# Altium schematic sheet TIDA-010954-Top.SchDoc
size 431 x 279 mm; Date: Not shown in title block; ApprovedBy: Not shown in title block; CheckedBy: Not shown in title block; Author: Not shown in title block; CompanyName: Not shown in title block; Engineer: Not shown in title block; Organization: Not shown in title block; Address1: Not shown in title block; Address2: Not shown in title block; Address3: Not shown in title block; Address4: Not shown in title block; DocumentNumber: 2; Revision: Use project parameter SCH_Rev; SheetNumber: 1; SheetTotal: 9; PageSetup: Record=PageOptions¦CenterHorizontal=True¦CenterVertical=True¦PrintScale=1.00¦XCorrection=1.00¦YCorrection=1.00¦PrintKind=0¦BorderSize=5000000¦LeftOffset=0¦BottomOffset=0¦Orientation=2¦PaperLength=1000¦PaperWidth=1000¦Scale=100¦PaperSource=15¦PrintQuality=600¦MediaType=1¦DitherType=10¦PaperKind=Letter¦PrintScaleMode=1
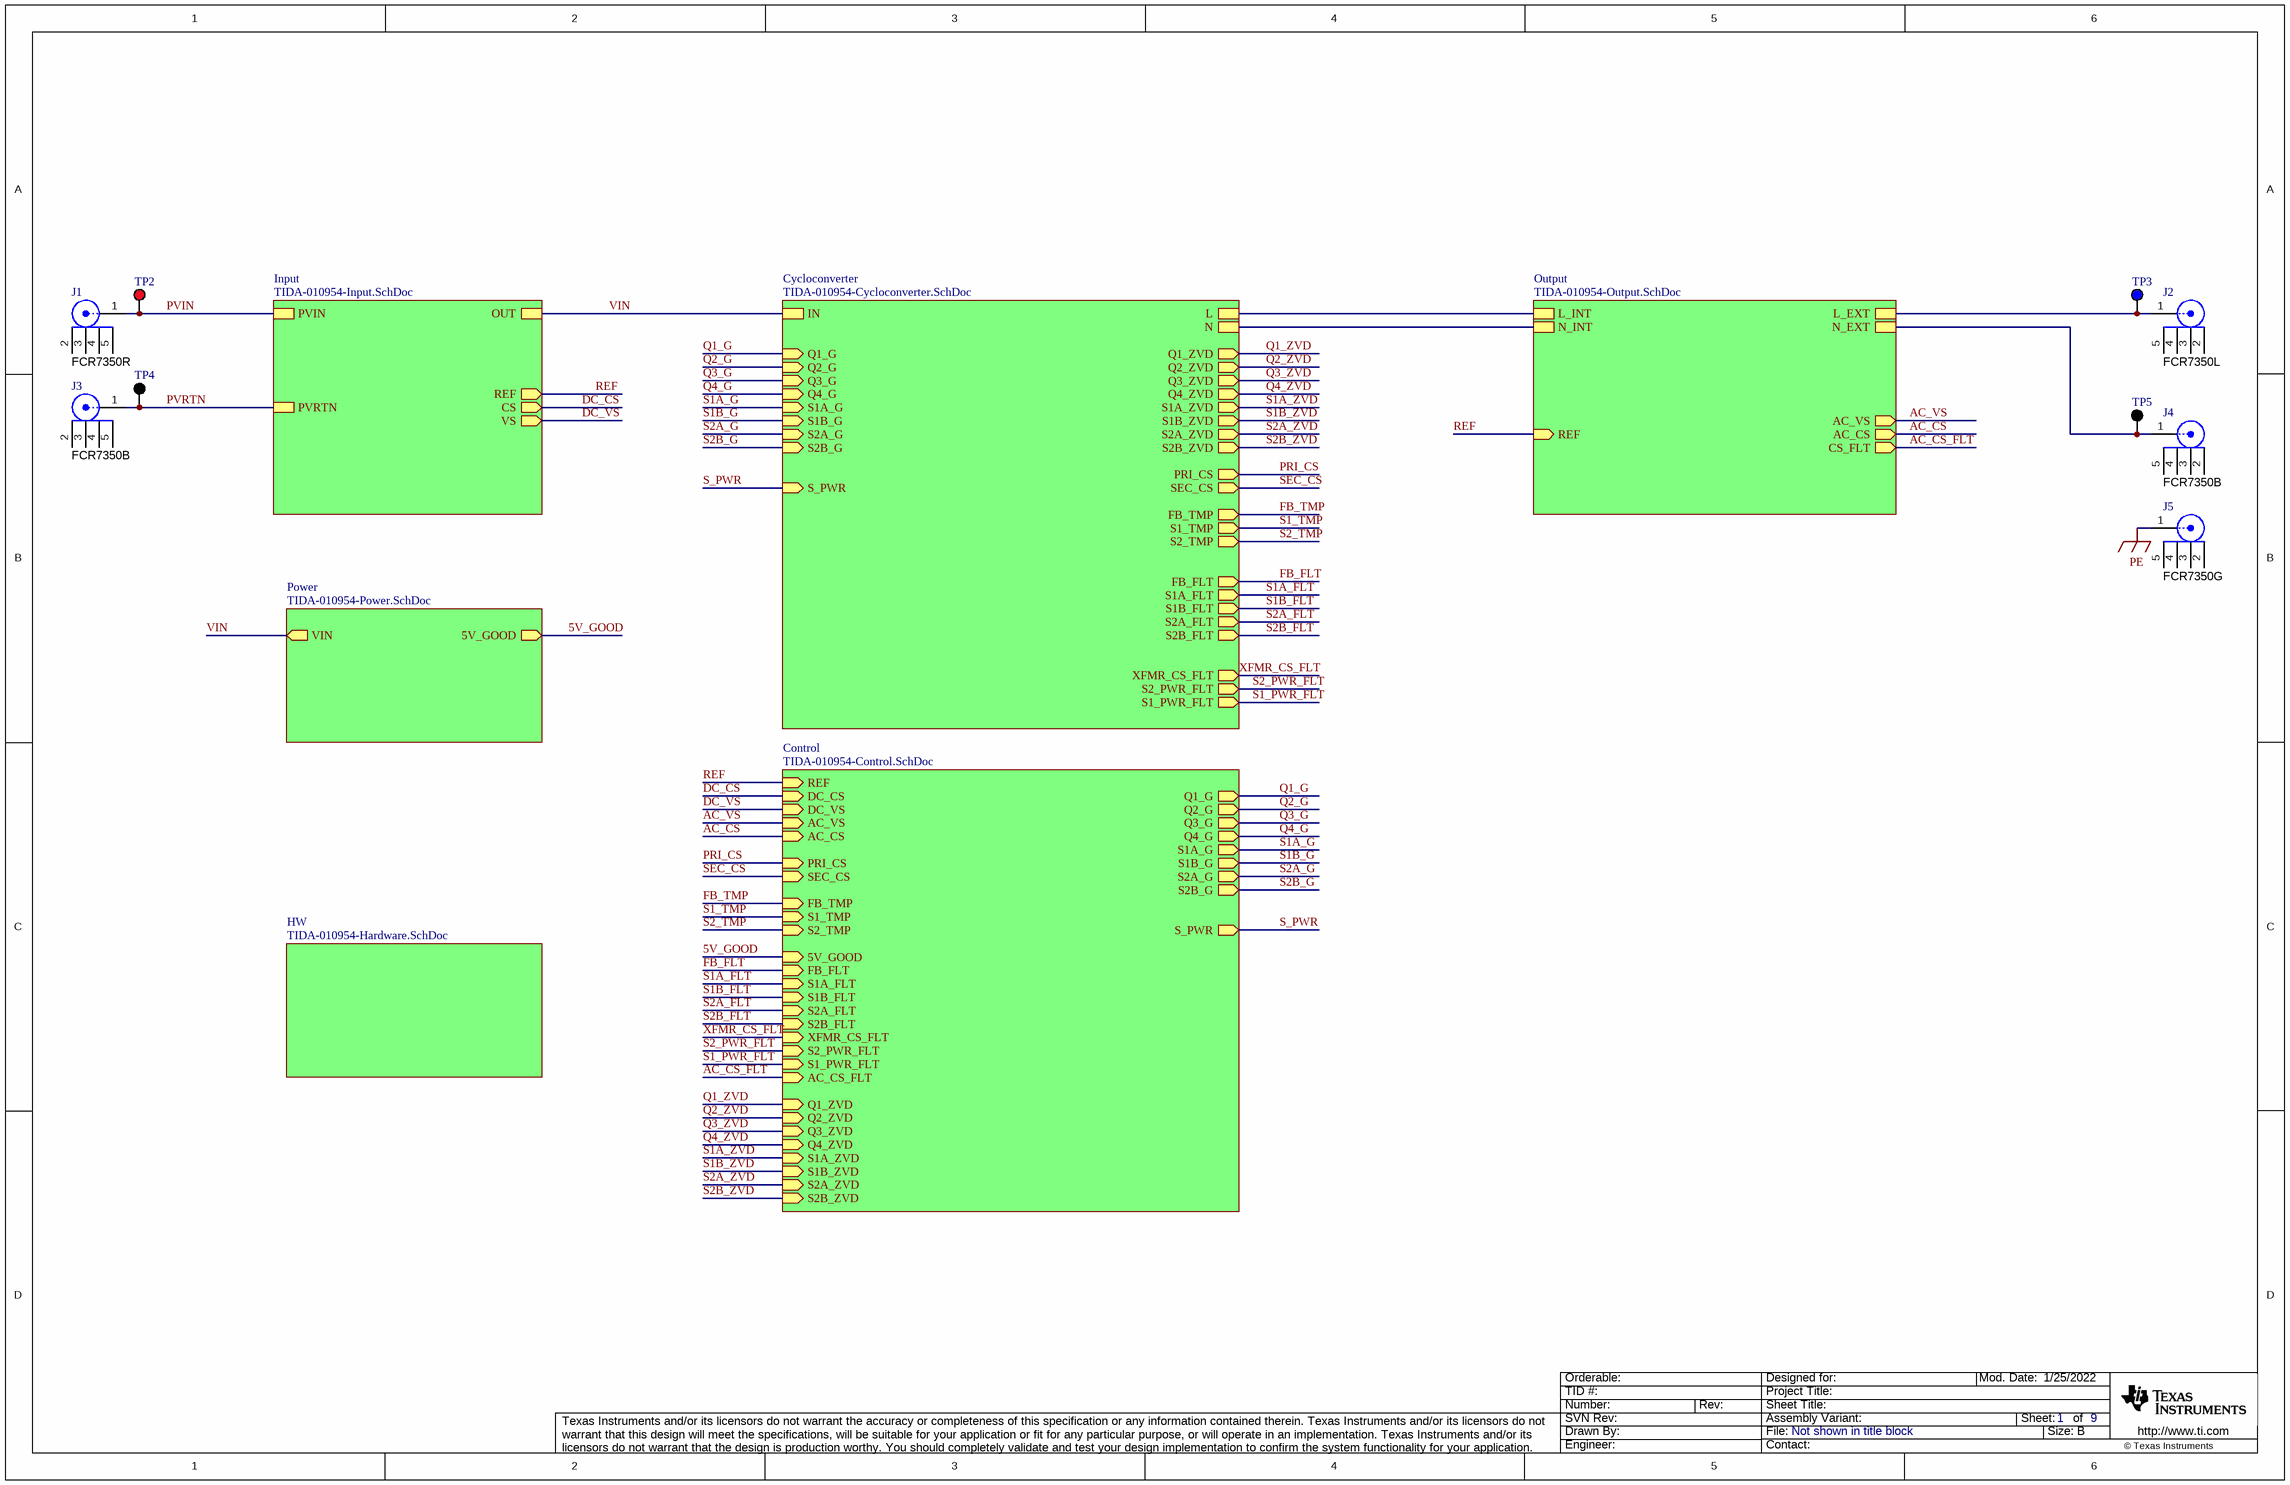
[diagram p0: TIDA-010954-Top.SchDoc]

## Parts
J1  FCR7350R  [Cliff_FCR7350R]
J2  FCR7350L  [FP-FCR7350L_CONN_BANANA_JACK-MFG]
J3  FCR7350B  [Cliff_FCR7350B]
J4  FCR7350B  [Cliff_FCR7350B]
J5  FCR7350G  [FP-FCR7350G_CONN_BANANA_JACK-MFG]
TP2  5010  [Keystone5010]  (value not drawn)
TP3  5127  [Keystone5127]  (value not drawn)
TP4  5011  [Keystone5011]  (value not drawn)
TP5  5011  [Keystone5011]  (value not drawn)

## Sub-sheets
Control = TIDA-010954-Control.SchDoc: Q1_G (out), Q2_G (out), Q3_G (out), Q4_G (out), S1A_G (out), S1B_G (out), S2A_G (out), S2B_G (out), S_PWR (out), 5V_GOOD (in), DC_CS (in), DC_VS (in), REF (in), AC_CS (in), AC_VS (in), PRI_CS (in), SEC_CS (in), FB_FLT (in), S1_PWR_FLT (in), XFMR_CS_FLT (in), S1A_FLT (in), S2_PWR_FLT (in), S2A_FLT (in), AC_CS_FLT (in), S1_TMP (in), S2_TMP (in), FB_TMP (in), Q2_ZVD (in), Q1_ZVD (in), Q4_ZVD (in), Q3_ZVD (in), S1A_ZVD (in), S1B_ZVD (in), S2A_ZVD (in), S2B_ZVD (in), S1B_FLT (in), S2B_FLT (in)
Cycloconverter = TIDA-010954-Cycloconverter.SchDoc: IN, N, L, Q1_G (in), Q2_G (in), Q3_G (in), Q4_G (in), S1A_G (in), S1B_G (in), S2A_G (in), S2B_G (in), S_PWR (in), PRI_CS (out), SEC_CS (out), FB_FLT (out), Q2_ZVD (out), Q1_ZVD (out), Q4_ZVD (out), Q3_ZVD (out), S1_PWR_FLT (out), XFMR_CS_FLT (out), S1A_ZVD (out), S1B_ZVD (out), S1A_FLT (out), S1_TMP (out), S2_PWR_FLT (out), S2A_ZVD (out), S2B_ZVD (out), S2A_FLT (out), S2_TMP (out), FB_TMP (out), S2B_FLT (out), S1B_FLT (out)
HW = TIDA-010954-Hardware.SchDoc: no entries
Input = TIDA-010954-Input.SchDoc: OUT, PVIN, PVRTN, CS (out), VS (out), REF (out)
Output = TIDA-010954-Output.SchDoc: L_INT, N_INT, L_EXT, N_EXT, CS_FLT (out), AC_CS (out), REF (in), AC_VS (out)
Power = TIDA-010954-Power.SchDoc: VIN (out), 5V_GOOD (out)

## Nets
PE: J5.1
5V_GOOD: sheet Power/5V_GOOD, sheet Control/5V_GOOD
AC_CS: sheet Output/AC_CS, sheet Control/AC_CS
AC_CS_FLT: sheet Output/CS_FLT, sheet Control/AC_CS_FLT
AC_VS: sheet Output/AC_VS, sheet Control/AC_VS
DC_CS: sheet Input/CS, sheet Control/DC_CS
DC_VS: sheet Input/VS, sheet Control/DC_VS
FB_FLT: sheet Cycloconverter/FB_FLT, sheet Control/FB_FLT
FB_TMP: sheet Cycloconverter/FB_TMP, sheet Control/FB_TMP
PRI_CS: sheet Cycloconverter/PRI_CS, sheet Control/PRI_CS
PVIN: J1.1 TP2.1 ; sheet Input/PVIN
PVRTN: J3.1 TP4.1 ; sheet Input/PVRTN
Q1_G: sheet Cycloconverter/Q1_G, sheet Control/Q1_G
Q1_ZVD: sheet Cycloconverter/Q1_ZVD, sheet Control/Q1_ZVD
Q2_G: sheet Cycloconverter/Q2_G, sheet Control/Q2_G
Q2_ZVD: sheet Cycloconverter/Q2_ZVD, sheet Control/Q2_ZVD
Q3_G: sheet Cycloconverter/Q3_G, sheet Control/Q3_G
Q3_ZVD: sheet Cycloconverter/Q3_ZVD, sheet Control/Q3_ZVD
Q4_G: sheet Cycloconverter/Q4_G, sheet Control/Q4_G
Q4_ZVD: sheet Cycloconverter/Q4_ZVD, sheet Control/Q4_ZVD
REF: sheet Input/REF, sheet Output/REF, sheet Control/REF
S1_PWR_FLT: sheet Cycloconverter/S1_PWR_FLT, sheet Control/S1_PWR_FLT
S1_TMP: sheet Cycloconverter/S1_TMP, sheet Control/S1_TMP
S1A_FLT: sheet Cycloconverter/S1A_FLT, sheet Control/S1A_FLT
S1A_G: sheet Cycloconverter/S1A_G, sheet Control/S1A_G
S1A_ZVD: sheet Cycloconverter/S1A_ZVD, sheet Control/S1A_ZVD
S1B_FLT: sheet Cycloconverter/S1B_FLT, sheet Control/S1B_FLT
S1B_G: sheet Cycloconverter/S1B_G, sheet Control/S1B_G
S1B_ZVD: sheet Cycloconverter/S1B_ZVD, sheet Control/S1B_ZVD
S2_PWR_FLT: sheet Cycloconverter/S2_PWR_FLT, sheet Control/S2_PWR_FLT
S2_TMP: sheet Cycloconverter/S2_TMP, sheet Control/S2_TMP
S2A_FLT: sheet Cycloconverter/S2A_FLT, sheet Control/S2A_FLT
S2A_G: sheet Cycloconverter/S2A_G, sheet Control/S2A_G
S2A_ZVD: sheet Cycloconverter/S2A_ZVD, sheet Control/S2A_ZVD
S2B_FLT: sheet Cycloconverter/S2B_FLT, sheet Control/S2B_FLT
S2B_G: sheet Cycloconverter/S2B_G, sheet Control/S2B_G
S2B_ZVD: sheet Cycloconverter/S2B_ZVD, sheet Control/S2B_ZVD
S_PWR: sheet Cycloconverter/S_PWR, sheet Control/S_PWR
SEC_CS: sheet Cycloconverter/SEC_CS, sheet Control/SEC_CS
VIN: sheet Power/VIN, sheet Input/OUT, sheet Cycloconverter/IN
XFMR_CS_FLT: sheet Cycloconverter/XFMR_CS_FLT, sheet Control/XFMR_CS_FLT
NetJ2_1: J2.1 TP3.1 ; sheet Output/L_EXT
NetJ4_1: J4.1 TP5.1 ; sheet Output/N_EXT
(unnamed): sheet Output/L_INT, sheet Cycloconverter/L
(unnamed): sheet Output/N_INT, sheet Cycloconverter/N  [a separate net that carries the same name]

Not connected (* = marked no-connect by the designer): J1 2 3 4 5; J2 2 3 4 5; J3 2 3 4 5; J4 2 3 4 5; J5 2 3 4 5

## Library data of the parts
J1 = CMP-0055799-1: Panel Socket, 24A, R/A, Gold, TH; Manufacturer: Cliff Electronic Components; CNHeader: FALSE; Gender: Female; Voltage_V: 1kV
J2 = CMP-0098295-2: Banana Test Connector, 4mm, Socket, PCB Mount, 24 A, 1 kV, Gold Plated Contacts, Blue; Manufacturer: CLIFF Electronic Components; Current_A: 24A; Voltage_V: 1kV; AEC Qualified: No; Conn Orientation: Right Angle; SizeZ_mm: 11.6mm; Standoff Height: 0.7mm
J3 J4 = CMP-0055798-1: Panel Socket, 24A, R/A, Gold, TH; Manufacturer: Cliff Electronic Components; CNHeader: FALSE; Gender: Female; Voltage_V: 1kV
J5 = CMP-0098294-2: Banana Test Connector, Socket, PCB Mount, 24 A, 1 kV, Gold Plated Contacts, Green; Manufacturer: CLIFF Electronic Components; Current_A: 24A; Voltage_V: 1kV; AEC Qualified: No; Conn Orientation: Right Angle; SizeZ_mm: 11.6mm; Standoff Height: 0.7mm
TP2 = CMP-0055147-2: Test Point, Multipurpose, Red, TH; Manufacturer: Keystone Electronics; CT: TRUE; ContactFinish: Silver; Green_Lifecycle: Active; CNHeader: FALSE; Green_REACh: Passed
TP3 = CMP-0055156-2: Test Point, Multipurpose, Blue, TH; Manufacturer: Keystone Electronics; CT: TRUE; ContactFinish: Silver; CNHeader: FALSE; Green_REACh: Passed; Green_Lifecycle: Active
TP4 TP5 = CMP-0055148-2: Test Point, Multipurpose, Black, TH; Manufacturer: Keystone Electronics; CNHeader: FALSE; ContactFinish: Silver; Green_REACh: Passed; Green_Lifecycle: Active; CT: TRUE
